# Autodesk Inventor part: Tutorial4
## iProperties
Shininess: 64.0
Length Units: 11269
Angle Units: 11279
Time Units: 11290
Mass Units: 11283
Length Display Precision: 3
Angle Display Precision: 2
Compacted: True
Part Number: Tutorial4
Document SubType Name: Modeling
Created: 2002-12
Designer: deepak
Density: 1 g/cm^3
Density: 0.0
Volumn: 0.0
Area: 0.0
PropertySet Name: Model Information
Control State: 0
Master: False
Checked Out: False
Author: deepak
